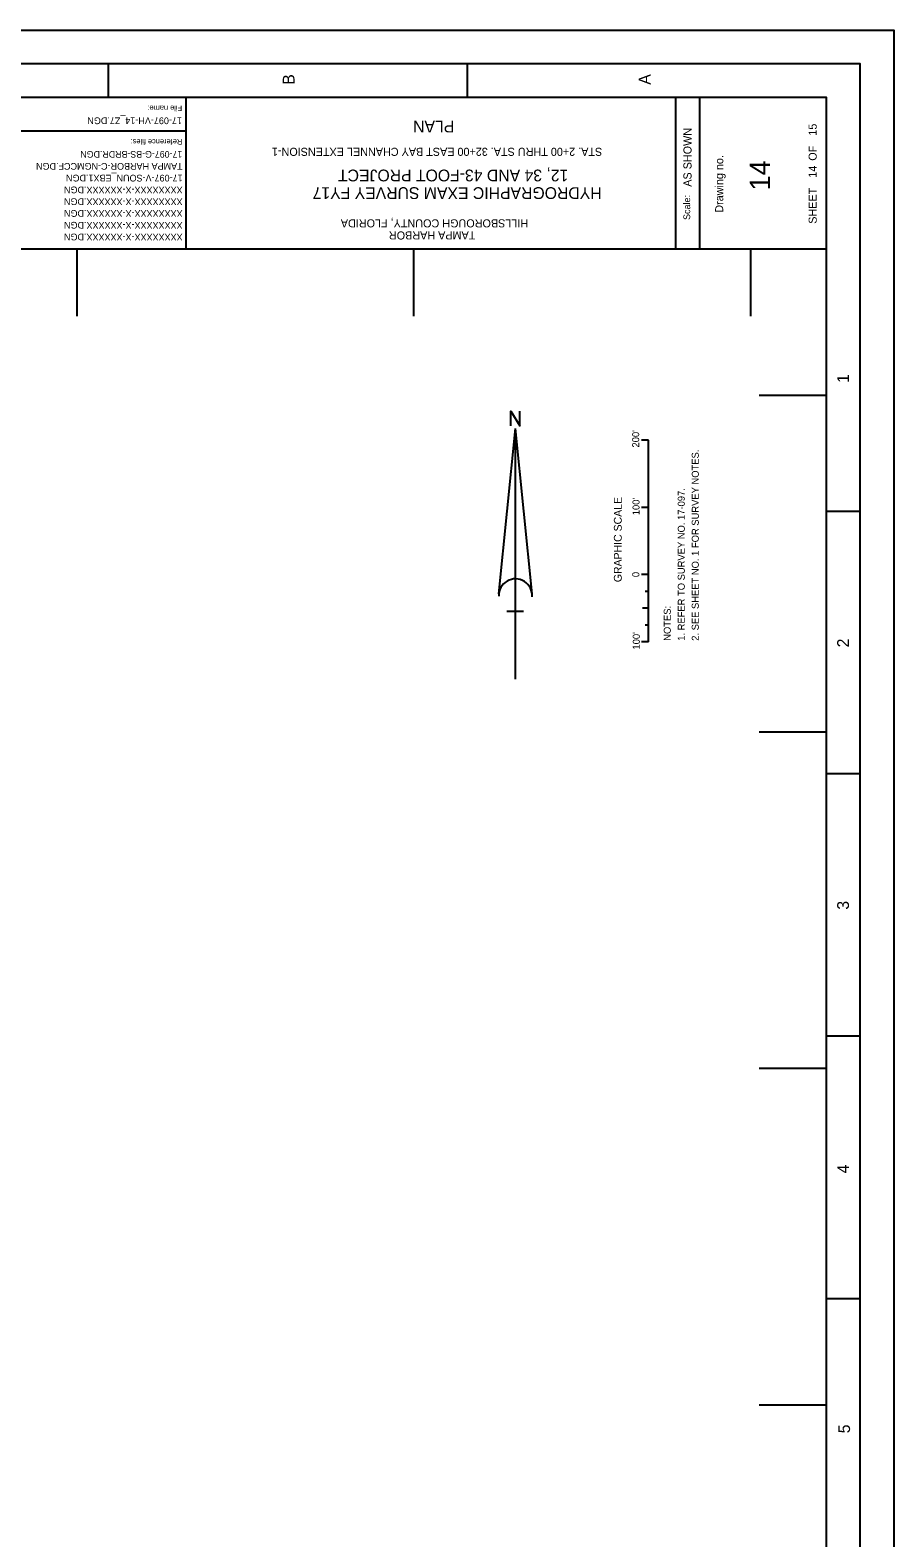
# Model space of a CAD drawing. Extents: x 516313 to 519713, y 1302143 to 1306543.
# Drawn here: x 518430 to 519713, y 1304303 to 1306543 of the extents above; entities that cross this region are included whole.
import ezdxf

# ---------------------------------------------------------------- set-up
doc = ezdxf.new("R2010")
doc.units = 0
for name, color, linetype in [('G-ANNO-NPLT', 7, 'Continuous'), ('G-ANNO-TEXT-DRWG', 7, 'Continuous'), ('G-ANNO-TEXT-PROJ', 7, 'Continuous'), ('G-ANNO-TEXT-TTLB', 7, 'Continuous'), ('G-ANNO-TTLB', 7, 'Continuous'), ('V-ANNO-NOTE', 7, 'Continuous'), ('V-ANNO-SYMB', 7, 'Continuous'), ('V-TOPO-COOR-STAT', 7, 'Continuous')]:
    doc.layers.add(name, color=color, linetype=linetype)

msp = doc.modelspace()

# ---------------------------------------------------------------- linework, layer by layer
at = {"layer": 'G-ANNO-NPLT'}
msp.add_lwpolyline([(516312.5, 1302142.9), (516312.5, 1306542.8), (519712.5, 1306542.8), (519712.5, 1302142.9)], close=True, dxfattribs=at)
msp.add_lwpolyline([(519662.5, 1306543), (519712.5, 1306543), (519712.5, 1306493)], dxfattribs=at)
at = {"layer": 'G-ANNO-TTLB'}
for p, q in [((518545.9, 1306492.8), (518545.9, 1306442.8)), ((519079.2, 1306492.8), (519079.2, 1306442.8)), ((518661.8, 1306217.8), (518661.8, 1306442.8)), ((519388.8, 1306217.8), (519388.8, 1306442.8)), ((519424.5, 1306217.8), (519424.5, 1306442.8)), ((518310.4, 1306393.5), (518661.8, 1306393.5)), ((516412.5, 1306217.8), (519612.5, 1306217.8)), ((519662.5, 1305827.9), (519612.5, 1305827.9)), ((519662.5, 1305437.9), (519612.5, 1305437.9)), ((519662.5, 1305047.9), (519612.5, 1305047.9)), ((519662.5, 1304657.9), (519612.5, 1304657.9))]:
    msp.add_line(p, q, dxfattribs=at)
for points in [[(519662.5, 1302192.9), (519662.5, 1306492.8), (516362.5, 1306492.8), (516362.5, 1302192.9)], [(516412.5, 1306442.8), (516412.5, 1302317.9), (519612.5, 1302317.9), (519612.5, 1306442.8)]]:
    msp.add_lwpolyline(points, close=True, dxfattribs=at)
at = {"layer": 'V-ANNO-NOTE'}
for p, q in [((519348, 1305933.9), (519337.6, 1305933.9)), ((519348, 1305633.9), (519348, 1305933.9)), ((519348, 1305833.9), (519337.6, 1305833.9)), ((519348, 1305733.9), (519337.6, 1305733.9)), ((519348, 1305733.9), (519337.6, 1305733.9)), ((519348, 1305733.9), (519343, 1305733.9)), ((519348, 1305708.9), (519343.2, 1305708.9)), ((519348, 1305683.9), (519339.5, 1305683.9)), ((519348, 1305658.9), (519343.2, 1305658.9)), ((519348, 1305633.9), (519337.6, 1305633.9))]:
    msp.add_line(p, q, dxfattribs=at)
at = {"layer": 'V-ANNO-SYMB'}
for p, q in [((519126, 1305705.2), (519150.7, 1305951)), ((519150.7, 1305578.7), (519150.7, 1305951)), ((519175.4, 1305705.2), (519150.7, 1305951)), ((519162.5, 1305679.2), (519137.7, 1305679.2))]:
    msp.add_line(p, q, dxfattribs=at)
msp.add_lwpolyline([(519143.9, 1305955), (519143.9, 1305976.7), (519157.4, 1305955), (519157.4, 1305976.7)], dxfattribs=at)
msp.add_arc((519150.7, 1305702.8), 24.8, 355.2984, 182.0673, dxfattribs=at)
at = {"layer": 'V-TOPO-COOR-STAT'}
for p, q in [((518500, 1306117.8), (518500, 1306217.8)), ((519000, 1306117.8), (519000, 1306217.8)), ((519500, 1306117.8), (519500, 1306217.8)), ((519612.5, 1306000), (519512.5, 1306000)), ((519612.5, 1305500), (519512.5, 1305500)), ((519612.5, 1305000), (519512.5, 1305000)), ((519612.5, 1304500), (519512.5, 1304500))]:
    msp.add_line(p, q, dxfattribs=at)

# ---------------------------------------------------------------- texts
at = {"layer": 'G-ANNO-TEXT-DRWG'}
for s, height, rotation, p in [('17-097-VH-14_Z7.DGN', 10, 180, (518655.4, 1306413.3)), ('PLAN', 17.5, 180, (519059.8, 1306408.4)), (' 14          15', 12, 90, (519598, 1306319.3)), ('STA. 2+00 THRU STA. 32+00 EAST BAY CHANNEL EXTENSION-1', 12, 180, (519279.5, 1306368.2)), ('TAMPA HARBOR-C-NGMCCF.DGN', 10, 180, (518656.4, 1306345.6)), ('14', 30, 90, (519528.7, 1306304.8)), ('17-097-V-SOUN_EBX1.DGN', 10, 180, (518656.4, 1306328.1)), ('XXXXXXXX-X-XXXXXX.DGN', 10, 180, (518656.4, 1306310.6)), ('XXXXXXXX-X-XXXXXX.DGN', 10, 180, (518656.4, 1306293.1)), ('XXXXXXXX-X-XXXXXX.DGN', 10, 180, (518656.4, 1306275.6)), ('XXXXXXXX-X-XXXXXX.DGN', 10, 180, (518656.4, 1306258.1)), ('XXXXXXXX-X-XXXXXX.DGN', 10, 180, (518656.4, 1306240.6))]:
    msp.add_text(s, height=height, rotation=rotation, dxfattribs=at).set_placement(p)
at = {"layer": 'G-ANNO-TEXT-PROJ'}
for s, height, p in [('17-097-G-BS-BRDR.DGN', 9.8, (518656, 1306363.3)), ('12, 34 AND 43-FOOT PROJECT', 17.5, (519229.2, 1306335.8)), ('HYDROGRAPHIC EXAM SURVEY FY17', 17.5, (519278.6, 1306309.6)), ('HILLSBOROUGH COUNTY, FLORIDA', 12, (519169.5, 1306261.9)), ('TAMPA HARBOR', 12, (519091.1, 1306243.9))]:
    msp.add_text(s, height=height, rotation=180, dxfattribs=at).set_placement(p)
at = {"layer": 'G-ANNO-TEXT-TTLB'}
for s, height, rotation, p in [('File name:', 8, 180, (518655.7, 1306430.9)), ('AS SHOWN', 12, 90, (519412.1, 1306310.3)), ('Reference files:', 8, 180, (518655.9, 1306381)), ('SHEET         OF', 12, 90, (519598, 1306255.3)), ('Drawing no.', 12, 90, (519459.2, 1306271.7)), ('Scale:', 10, 90, (519410.1, 1306260.9))]:
    msp.add_text(s, height=height, rotation=rotation, dxfattribs=at).set_placement(p)
at = {"layer": 'G-ANNO-TTLB'}
for s, p in [('B', (518822.6, 1306461.9)), ('A', (519351.3, 1306461.9)), ('1', (519645.9, 1306018.9)), ('2', (519645.9, 1305625.8)), ('3', (519645.9, 1305236)), ('4', (519645.9, 1304844.2)), ('5', (519647.5, 1304458))]:
    msp.add_text(s, height=17.5, rotation=90, dxfattribs=at).set_placement(p)
at = {"layer": 'V-ANNO-NOTE'}
for s, height, p in [("200'", 10.42, (519334.4, 1305922.8)), ('2. SEE SHEET NO. 1 FOR SURVEY NOTES.', 10.416, (519422.9, 1305635.6)), ('GRAPHIC SCALE', 11.666, (519308.5, 1305722.7)), ("100'", 10.42, (519334.9, 1305822.2)), ('1. REFER TO SURVEY NO. 17-097.', 10.416, (519402.1, 1305635.6)), ('0', 10.4, (519334.6, 1305730.2)), ('NOTES:', 10.42, (519381.3, 1305635.6)), ("100'", 10.42, (519335.3, 1305622.6))]:
    msp.add_text(s, height=height, rotation=90, dxfattribs=at).set_placement(p)

doc.saveas('drawing.dxf')
